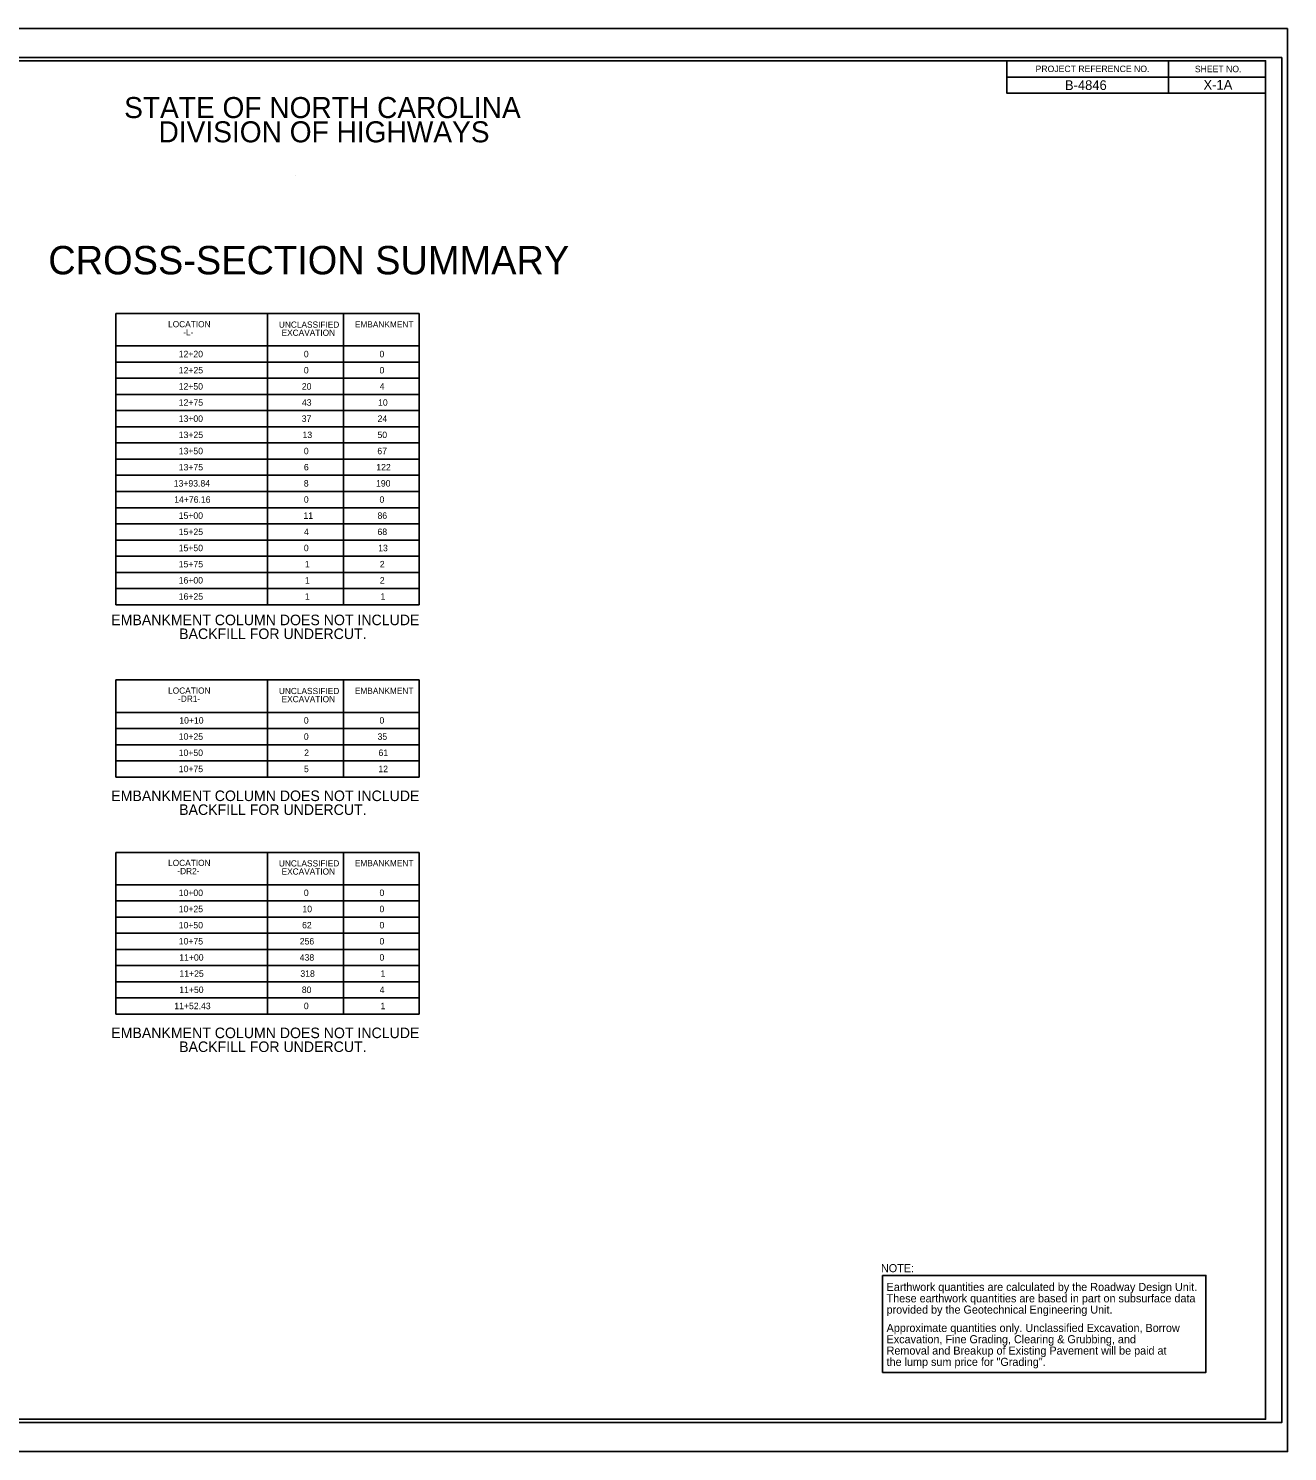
# Model space of a CAD drawing. Extents: x 573898.1 to 573931.8, y -53269.2 to -53247.2.
# Drawn here: x 573912.29 to 573931.77, y -53269.22 to -53247.22 of the extents above; entities that cross this region are included whole.
import ezdxf

# ---------------------------------------------------------------- set-up
doc = ezdxf.new("R2010")
doc.units = 0
for name, color, linetype in [('Sheet Cutting Line CELL', 7, 'Continuous'), ('Sheet Data Field CELL', 7, 'Continuous'), ('Sheet Plot Border Inside CELL', 7, 'Continuous'), ('Sheet Plot Border Outside CELL', 7, 'Continuous'), ('Sheet Summary CELL', 7, 'Continuous'), ('Sheet Summary Combination CELL', 7, 'Continuous'), ('Sheet Summary Combination Grid CELL', 7, 'Continuous'), ('Sheet Summary Earthwork CELL', 7, 'Continuous')]:
    doc.layers.add(name, color=color, linetype=linetype)

msp = doc.modelspace()

# ---------------------------------------------------------------- linework, layer by layer
at = {"layer": 'Sheet Cutting Line CELL'}
for p, q in [((573931.766, -53247.225), (573898.086, -53247.225)), ((573898.086, -53269.225), (573931.766, -53269.225))]:
    msp.add_line(p, q, dxfattribs=at)
at = {"layer": 'Sheet Plot Border Inside CELL'}
msp.add_lwpolyline([(573931.676, -53247.674), (573898.346, -53247.674), (573898.346, -53268.776), (573931.676, -53268.776)], close=True, dxfattribs=at)
at = {"layer": 'Sheet Plot Border Outside CELL'}
msp.add_lwpolyline([(573931.766, -53247.225), (573898.086, -53247.225), (573898.086, -53269.225), (573931.766, -53269.225)], close=True, dxfattribs=at)
at = {"layer": 'Sheet Summary CELL'}
for p, q in [((573929.926, -53247.726), (573929.926, -53248.226)), ((573927.425, -53247.976), (573931.426, -53247.976)), ((573927.425, -53248.226), (573931.426, -53248.226)), ((573916.418, -53249.501), (573916.418, -53249.501))]:
    msp.add_line(p, q, dxfattribs=at)
for points in [[(573931.426, -53247.725), (573901.426, -53247.725), (573901.426, -53268.725), (573931.426, -53268.725)], [(573927.425, -53247.725), (573931.426, -53247.725), (573931.426, -53248.226), (573927.425, -53248.226)]]:
    msp.add_lwpolyline(points, close=True, dxfattribs=at)
at = {"layer": 'Sheet Summary Combination Grid CELL'}
for p, q in [((573913.647, -53251.633), (573918.336, -53251.633)), ((573913.647, -53251.633), (573913.647, -53256.133)), ((573915.992, -53251.633), (573915.992, -53256.133)), ((573917.166, -53251.633), (573917.166, -53256.133)), ((573918.336, -53251.633), (573918.336, -53256.133)), ((573913.647, -53252.133), (573918.336, -53252.133)), ((573913.647, -53252.383), (573918.336, -53252.383)), ((573913.647, -53252.633), (573918.336, -53252.633)), ((573913.647, -53252.883), (573918.336, -53252.883)), ((573913.647, -53253.133), (573918.336, -53253.133)), ((573913.647, -53253.383), (573918.336, -53253.383)), ((573913.647, -53253.633), (573918.336, -53253.633)), ((573913.647, -53253.883), (573918.336, -53253.883)), ((573913.647, -53254.133), (573918.336, -53254.133)), ((573913.647, -53254.383), (573918.336, -53254.383)), ((573913.647, -53254.633), (573918.336, -53254.633)), ((573913.647, -53254.883), (573918.336, -53254.883)), ((573913.647, -53255.133), (573918.336, -53255.133)), ((573913.647, -53255.383), (573918.336, -53255.383)), ((573913.647, -53255.633), (573918.336, -53255.633)), ((573913.647, -53255.883), (573918.336, -53255.883)), ((573913.647, -53256.133), (573918.336, -53256.133)), ((573913.647, -53257.297), (573918.336, -53257.297)), ((573913.647, -53257.297), (573913.647, -53258.797)), ((573915.992, -53257.297), (573915.992, -53258.797)), ((573917.166, -53257.297), (573917.166, -53258.797)), ((573918.336, -53257.297), (573918.336, -53258.797)), ((573913.647, -53257.797), (573918.336, -53257.797)), ((573913.647, -53258.047), (573918.336, -53258.047)), ((573913.647, -53258.297), (573918.336, -53258.297)), ((573913.647, -53258.547), (573918.336, -53258.547)), ((573913.647, -53258.797), (573918.336, -53258.797)), ((573913.647, -53259.962), (573918.336, -53259.962)), ((573913.647, -53259.962), (573913.647, -53262.462)), ((573915.992, -53259.962), (573915.992, -53262.462)), ((573917.166, -53259.962), (573917.166, -53262.462)), ((573918.336, -53259.962), (573918.336, -53262.462)), ((573913.647, -53260.462), (573918.336, -53260.462)), ((573913.647, -53260.712), (573918.336, -53260.712)), ((573913.647, -53260.962), (573918.336, -53260.962)), ((573913.647, -53261.212), (573918.336, -53261.212)), ((573913.647, -53261.462), (573918.336, -53261.462)), ((573913.647, -53261.712), (573918.336, -53261.712)), ((573913.647, -53261.962), (573918.336, -53261.962)), ((573913.647, -53262.212), (573918.336, -53262.212)), ((573913.647, -53262.462), (573918.336, -53262.462))]:
    msp.add_line(p, q, dxfattribs=at)
at = {"layer": 'Sheet Summary Earthwork CELL'}
msp.add_lwpolyline([(573925.503, -53266.501), (573930.504, -53266.501), (573930.504, -53268.002), (573925.503, -53268.002)], close=True, dxfattribs=at)

# ---------------------------------------------------------------- texts
at = {"layer": 'Sheet Data Field CELL'}
for s, p in [('B-4846', (573928.323, -53248.176)), ('X-1A', (573930.466, -53248.17))]:
    msp.add_text(s, height=0.15, dxfattribs=at).set_placement(p)
at = {"layer": 'Sheet Summary CELL'}
for s, height, p in [('PROJECT REFERENCE NO.', 0.1, (573927.869, -53247.899)), ('SHEET NO.', 0.1, (573930.332, -53247.901)), ('STATE OF NORTH CAROLINA', 0.325, (573913.774, -53248.61)), ('DIVISION OF HIGHWAYS', 0.325, (573914.306, -53248.985)), ('CROSS-SECTION SUMMARY', 0.439, (573912.601, -53251.026))]:
    msp.add_text(s, height=height, dxfattribs=at).set_placement(p)
at = {"layer": 'Sheet Summary Combination CELL'}
for s, height, p in [('LOCATION', 0.096, (573914.454, -53251.844)), ('-L-', 0.096, (573914.687, -53251.97)), ('UNCLASSIFIED', 0.096, (573916.167, -53251.851)), ('EXCAVATION', 0.096, (573916.209, -53251.977)), ('EMBANKMENT', 0.096, (573917.342, -53251.847)), ('12+20', 0.1, (573914.618, -53252.308)), ('0', 0.1, (573916.553, -53252.308)), ('0', 0.1, (573917.723, -53252.308)), ('12+25', 0.1, (573914.619, -53252.558)), ('0', 0.1, (573916.553, -53252.558)), ('0', 0.1, (573917.723, -53252.558)), ('12+50', 0.1, (573914.618, -53252.808)), ('20', 0.1, (573916.522, -53252.808)), ('4', 0.1, (573917.726, -53252.808)), ('12+75', 0.1, (573914.619, -53253.057)), ('43', 0.1, (573916.524, -53253.057)), ('10', 0.1, (573917.701, -53253.057)), ('13+00', 0.1, (573914.618, -53253.307)), ('37', 0.1, (573916.52, -53253.307)), ('24', 0.1, (573917.694, -53253.307)), ('13+25', 0.1, (573914.619, -53253.557)), ('13', 0.1, (573916.533, -53253.557)), ('50', 0.1, (573917.692, -53253.557)), ('13+50', 0.1, (573914.618, -53253.807)), ('0', 0.1, (573916.553, -53253.807)), ('67', 0.1, (573917.69, -53253.807)), ('13+75', 0.1, (573914.619, -53254.057)), ('6', 0.1, (573916.554, -53254.057)), ('122', 0.1, (573917.674, -53254.057)), ('13+93.84', 0.1, (573914.541, -53254.307)), ('8', 0.1, (573916.553, -53254.307)), ('190', 0.1, (573917.67, -53254.307)), ('14+76.16', 0.1, (573914.548, -53254.557)), ('0', 0.1, (573916.553, -53254.557)), ('0', 0.1, (573917.723, -53254.557)), ('15+00', 0.1, (573914.618, -53254.806)), ('11', 0.1, (573916.547, -53254.806)), ('86', 0.1, (573917.692, -53254.806)), ('15+25', 0.1, (573914.619, -53255.056)), ('4', 0.1, (573916.556, -53255.056)), ('68', 0.1, (573917.692, -53255.056)), ('15+50', 0.1, (573914.618, -53255.306)), ('0', 0.1, (573916.553, -53255.306)), ('13', 0.1, (573917.703, -53255.306)), ('15+75', 0.1, (573914.619, -53255.556)), ('1', 0.1, (573916.569, -53255.556)), ('2', 0.1, (573917.728, -53255.556)), ('16+00', 0.1, (573914.618, -53255.806)), ('1', 0.1, (573916.569, -53255.806)), ('2', 0.1, (573917.728, -53255.806)), ('16+25', 0.1, (573914.619, -53256.056)), ('1', 0.1, (573916.569, -53256.056)), ('1', 0.1, (573917.739, -53256.056)), ('EMBANKMENT COLUMN DOES NOT INCLUDE', 0.1632, (573913.575, -53256.45)), ('BACKFILL FOR UNDERCUT.', 0.1632, (573914.625, -53256.664)), ('LOCATION', 0.096, (573914.454, -53257.509)), ('-DR1-', 0.096, (573914.608, -53257.635)), ('UNCLASSIFIED', 0.096, (573916.167, -53257.515)), ('EXCAVATION', 0.096, (573916.209, -53257.641)), ('EMBANKMENT', 0.096, (573917.342, -53257.512)), ('10+10', 0.1, (573914.627, -53257.972)), ('0', 0.1, (573916.553, -53257.972)), ('0', 0.1, (573917.723, -53257.972)), ('10+25', 0.1, (573914.619, -53258.222)), ('0', 0.1, (573916.553, -53258.222)), ('35', 0.1, (573917.693, -53258.222)), ('10+50', 0.1, (573914.618, -53258.472)), ('2', 0.1, (573916.558, -53258.472)), ('61', 0.1, (573917.708, -53258.472)), ('10+75', 0.1, (573914.619, -53258.722)), ('5', 0.1, (573916.555, -53258.722)), ('12', 0.1, (573917.706, -53258.722)), ('EMBANKMENT COLUMN DOES NOT INCLUDE', 0.1632, (573913.575, -53259.169)), ('BACKFILL FOR UNDERCUT.', 0.1632, (573914.625, -53259.383)), ('LOCATION', 0.096, (573914.454, -53260.173)), ('-DR2-', 0.096, (573914.597, -53260.299)), ('UNCLASSIFIED', 0.096, (573916.167, -53260.18)), ('EXCAVATION', 0.096, (573916.209, -53260.306)), ('EMBANKMENT', 0.096, (573917.342, -53260.176)), ('10+00', 0.1, (573914.618, -53260.637)), ('0', 0.1, (573916.553, -53260.637)), ('0', 0.1, (573917.723, -53260.637)), ('10+25', 0.1, (573914.619, -53260.887)), ('10', 0.1, (573916.531, -53260.887)), ('0', 0.1, (573917.723, -53260.887)), ('10+50', 0.1, (573914.618, -53261.137)), ('62', 0.1, (573916.526, -53261.137)), ('0', 0.1, (573917.723, -53261.137)), ('10+75', 0.1, (573914.619, -53261.386)), ('256', 0.1, (573916.49, -53261.386)), ('0', 0.1, (573917.723, -53261.386)), ('11+00', 0.1, (573914.627, -53261.636)), ('438', 0.1, (573916.49, -53261.636)), ('0', 0.1, (573917.723, -53261.636)), ('11+25', 0.1, (573914.629, -53261.886)), ('318', 0.1, (573916.5, -53261.886)), ('1', 0.1, (573917.739, -53261.886)), ('11+50', 0.1, (573914.627, -53262.136)), ('80', 0.1, (573916.522, -53262.136)), ('4', 0.1, (573917.726, -53262.136)), ('11+52.43', 0.1, (573914.55, -53262.386)), ('0', 0.1, (573916.553, -53262.386)), ('1', 0.1, (573917.739, -53262.386)), ('EMBANKMENT COLUMN DOES NOT INCLUDE', 0.1632, (573913.575, -53262.834)), ('BACKFILL FOR UNDERCUT.', 0.1632, (573914.625, -53263.048))]:
    msp.add_text(s, height=height, dxfattribs=at).set_placement(p)
at = {"layer": 'Sheet Summary Earthwork CELL'}
for s, p in [('NOTE:', (573925.478, -53266.452)), ('Earthwork quantities are calculated by the Roadway Design Unit. ', (573925.565, -53266.743)), ('These earthwork quantities are based in part on subsurface data ', (573925.565, -53266.918)), ('provided by the Geotechnical Engineering Unit.', (573925.565, -53267.093)), ('Approximate quantities only. Unclassified Excavation, Borrow ', (573925.565, -53267.376)), ('Excavation, Fine Grading, Clearing & Grubbing, and', (573925.565, -53267.551)), ('Removal and Breakup of Existing Pavement will be paid at', (573925.565, -53267.726)), ('the lump sum price for "Grading".', (573925.565, -53267.901))]:
    msp.add_text(s, height=0.125, dxfattribs=at).set_placement(p)

doc.saveas('drawing.dxf')
